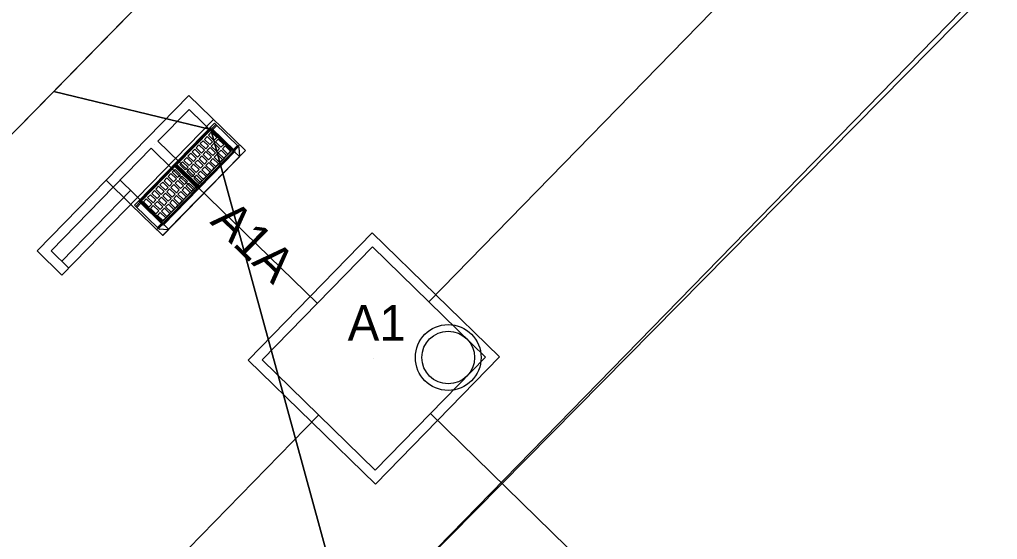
# Model space of a CAD drawing. Extents: x 2251012 to 2259557, y 13786786 to 13792525.
# Drawn here: x 2254977.12 to 2255026.62, y 13790879.97 to 13790906.29 of the extents above; entities that cross this region are included whole.
import ezdxf

# ---------------------------------------------------------------- set-up
doc = ezdxf.new("R2010")
doc.units = 0
for name, color, linetype in [('D_BOXES_1', 7, 'Continuous'), ('D_DRAIN_MISC', 7, 'Continuous'), ('D_DRAIN_NOTES_1', 7, 'Continuous'), ('D_DRN_AREA_A', 7, 'Continuous'), ('D_DRN_AREA_B', 7, 'Continuous'), ('D_DRN_AREA_X', 7, 'Continuous'), ('D_INLET_1', 7, 'Continuous'), ('D_PIPES_1', 7, 'Continuous')]:
    doc.layers.add(name, color=color, linetype=linetype)

msp = doc.modelspace()

# ---------------------------------------------------------------- linework, layer by layer
at = {"layer": 'D_BOXES_1'}
msp.add_line((2254879.145, 13790770.287), (2254992.252, 13790886.265), dxfattribs=at)
msp.add_lwpolyline([(2254997.838, 13790891.992), (2255031.955, 13790926.975), (2255100.904, 13790927.272)], dxfattribs=at)
at = {"layer": 'D_DRAIN_MISC'}
for p, q in [((2254986.768, 13790900.693), (2254986.768, 13790900.693)), ((2254983.948, 13790899.95), (2254983.948, 13790899.95)), ((2254984.843, 13790899.077), (2254984.843, 13790899.077)), ((2254986.096, 13790897.856), (2254986.096, 13790897.856)), ((2254983.277, 13790897.113), (2254983.277, 13790897.113)), ((2254992.181, 13790891.921), (2254992.181, 13790891.921)), ((2254997.838, 13790891.992), (2254997.838, 13790891.992)), ((2254995.045, 13790889.128), (2254995.045, 13790889.128)), ((2254992.252, 13790886.265), (2254992.252, 13790886.265)), ((2254997.909, 13790886.336), (2254997.909, 13790886.336))]:
    msp.add_line(p, q, dxfattribs=at)
at = {"layer": 'D_DRN_AREA_A'}
for p, q in [((2254978.852, 13790902.651), (2254976.227, 13790899.968)), ((2254986.79, 13790900.715), (2254978.852, 13790902.651)), ((2254993.845, 13790875.008), (2254986.79, 13790900.715))]:
    msp.add_line(p, q, dxfattribs=at)
at = {"layer": 'D_DRN_AREA_B'}
for p, q in [((2255005.214, 13790929.644), (2254978.852, 13790902.651)), ((2254978.852, 13790902.651), (2254986.79, 13790900.715)), ((2254986.79, 13790900.715), (2254993.845, 13790875.008))]:
    msp.add_line(p, q, dxfattribs=at)
at = {"layer": 'D_DRN_AREA_X'}
for p, q in [((2255062.918, 13790944.988), (2254993.845, 13790875.008)), ((2255005.214, 13790929.644), (2254978.852, 13790902.651)), ((2254993.845, 13790875.008), (2255037.337, 13790919.603)), ((2254976.227, 13790899.968), (2254982.409, 13790906.286)), ((2254978.852, 13790902.651), (2254976.227, 13790899.968)), ((2254986.79, 13790900.715), (2254978.852, 13790902.651)), ((2254978.852, 13790902.651), (2254986.79, 13790900.715)), ((2254993.845, 13790875.008), (2254986.79, 13790900.715)), ((2254986.79, 13790900.715), (2254993.845, 13790875.008))]:
    msp.add_line(p, q, dxfattribs=at)
at = {"layer": 'D_INLET_1'}
for p, q in [((2254985.685, 13790902.447), (2254978.005, 13790894.572)), ((2254988.549, 13790899.654), (2254985.685, 13790902.447)), ((2254985.694, 13790901.74), (2254984.123, 13790900.129)), ((2254987.842, 13790899.645), (2254985.694, 13790901.74)), ((2254986.938, 13790901.225), (2254979.258, 13790893.35)), ((2254986.986, 13790901.039), (2254983.894, 13790897.869)), ((2254986.808, 13790900.805), (2254985.001, 13790898.953)), ((2254986.813, 13790900.742), (2254985.064, 13790898.949)), ((2254986.81, 13790900.722), (2254985.084, 13790898.952)), ((2254988.025, 13790899.617), (2254986.808, 13790900.805)), ((2254987.943, 13790899.618), (2254986.81, 13790900.722)), ((2254987.962, 13790899.621), (2254986.813, 13790900.742)), ((2254986.842, 13790900.772), (2254987.046, 13790900.981)), ((2254986.893, 13790900.722), (2254987.097, 13790900.931)), ((2254988.216, 13790899.84), (2254986.986, 13790901.039)), ((2254984.123, 13790900.129), (2254986.328, 13790897.979)), ((2254986.406, 13790900.155), (2254986.264, 13790900.009)), ((2254986.406, 13790900.155), (2254986.681, 13790899.887)), ((2254986.614, 13790900.367), (2254986.472, 13790900.222)), ((2254986.472, 13790900.222), (2254986.746, 13790899.954)), ((2254986.614, 13790900.367), (2254986.888, 13790900.1)), ((2254986.821, 13790900.58), (2254986.679, 13790900.435)), ((2254986.679, 13790900.435), (2254986.954, 13790900.167)), ((2254987.096, 13790900.313), (2254986.821, 13790900.58)), ((2254986.954, 13790900.167), (2254987.096, 13790900.313)), ((2254987.031, 13790900.092), (2254987.173, 13790900.238)), ((2254987.449, 13790899.968), (2254987.173, 13790900.238)), ((2254983.774, 13790899.771), (2254978.712, 13790894.581)), ((2254983.774, 13790899.771), (2254985.979, 13790897.621)), ((2254988.248, 13790899.948), (2254984.059, 13790895.652)), ((2254987.842, 13790899.645), (2254984.351, 13790896.066)), ((2254988.546, 13790899.657), (2254984.357, 13790895.362)), ((2254988.549, 13790899.654), (2254984.36, 13790895.359)), ((2254985.991, 13790899.729), (2254985.849, 13790899.583)), ((2254985.991, 13790899.729), (2254986.266, 13790899.461)), ((2254986.199, 13790899.942), (2254986.056, 13790899.796)), ((2254986.056, 13790899.796), (2254986.331, 13790899.528)), ((2254986.199, 13790899.942), (2254986.473, 13790899.674)), ((2254986.264, 13790900.009), (2254986.539, 13790899.741)), ((2254986.331, 13790899.528), (2254986.473, 13790899.674)), ((2254986.539, 13790899.741), (2254986.681, 13790899.887)), ((2254986.615, 13790899.666), (2254986.757, 13790899.812)), ((2254986.615, 13790899.666), (2254986.892, 13790899.397)), ((2254986.746, 13790899.954), (2254986.888, 13790900.1)), ((2254986.757, 13790899.812), (2254987.034, 13790899.542)), ((2254986.823, 13790899.879), (2254986.965, 13790900.025)), ((2254986.823, 13790899.879), (2254987.1, 13790899.609)), ((2254986.965, 13790900.025), (2254987.242, 13790899.755)), ((2254987.031, 13790900.092), (2254987.307, 13790899.822)), ((2254987.1, 13790899.609), (2254987.242, 13790899.755)), ((2254987.176, 13790899.535), (2254987.318, 13790899.68)), ((2254987.307, 13790899.822), (2254987.449, 13790899.968)), ((2254987.318, 13790899.68), (2254987.593, 13790899.413)), ((2254987.384, 13790899.748), (2254987.526, 13790899.893)), ((2254987.384, 13790899.748), (2254987.658, 13790899.48)), ((2254987.801, 13790899.625), (2254987.526, 13790899.893)), ((2254987.94, 13790899.7), (2254988.144, 13790899.91)), ((2254987.991, 13790899.651), (2254988.195, 13790899.86)), ((2254988.27, 13790899.396), (2254988.231, 13790899.809)), ((2254988.26, 13790899.364), (2254984.643, 13790895.655)), ((2254985.576, 13790899.303), (2254985.434, 13790899.157)), ((2254985.434, 13790899.157), (2254985.708, 13790898.89)), ((2254985.576, 13790899.303), (2254985.85, 13790899.035)), ((2254985.783, 13790899.516), (2254985.641, 13790899.37)), ((2254985.641, 13790899.37), (2254985.916, 13790899.103)), ((2254985.783, 13790899.516), (2254986.058, 13790899.248)), ((2254985.849, 13790899.583), (2254986.123, 13790899.315)), ((2254985.916, 13790899.103), (2254986.058, 13790899.248)), ((2254985.993, 13790899.028), (2254986.135, 13790899.173)), ((2254986.123, 13790899.315), (2254986.266, 13790899.461)), ((2254986.135, 13790899.173), (2254986.411, 13790898.904)), ((2254986.2, 13790899.241), (2254986.342, 13790899.386)), ((2254986.2, 13790899.241), (2254986.477, 13790898.971)), ((2254987.962, 13790899.621), (2254986.214, 13790897.828)), ((2254986.216, 13790897.848), (2254987.943, 13790899.618)), ((2254988.025, 13790899.617), (2254986.219, 13790897.765)), ((2254986.342, 13790899.386), (2254986.619, 13790899.116)), ((2254987.93, 13790899.564), (2254986.357, 13790897.951)), ((2254986.408, 13790899.454), (2254986.55, 13790899.599)), ((2254986.408, 13790899.454), (2254986.684, 13790899.184)), ((2254986.55, 13790899.599), (2254986.827, 13790899.329)), ((2254986.684, 13790899.184), (2254986.827, 13790899.329)), ((2254986.761, 13790899.109), (2254986.903, 13790899.255)), ((2254986.892, 13790899.397), (2254987.034, 13790899.542)), ((2254986.903, 13790899.255), (2254987.178, 13790898.987)), ((2254986.969, 13790899.322), (2254987.111, 13790899.467)), ((2254986.969, 13790899.322), (2254987.243, 13790899.054)), ((2254987.111, 13790899.467), (2254987.385, 13790899.2)), ((2254987.176, 13790899.535), (2254987.451, 13790899.267)), ((2254987.243, 13790899.054), (2254987.385, 13790899.2)), ((2254987.451, 13790899.267), (2254987.593, 13790899.413)), ((2254987.658, 13790899.48), (2254987.801, 13790899.625)), ((2254987.996, 13790899.588), (2254988.243, 13790899.347)), ((2254983.166, 13790897.07), (2254984.972, 13790898.923)), ((2254983.229, 13790897.067), (2254984.977, 13790898.86)), ((2254983.248, 13790897.07), (2254984.975, 13790898.84)), ((2254984.844, 13790898.553), (2254984.986, 13790898.698)), ((2254986.19, 13790897.735), (2254984.972, 13790898.923)), ((2254986.107, 13790897.736), (2254984.975, 13790898.84)), ((2254986.127, 13790897.739), (2254984.977, 13790898.86)), ((2254985.26, 13790898.43), (2254984.986, 13790898.698)), ((2254986.219, 13790897.765), (2254985.001, 13790898.953)), ((2254986.214, 13790897.828), (2254985.064, 13790898.949)), ((2254986.216, 13790897.848), (2254985.084, 13790898.952)), ((2254985.368, 13790899.09), (2254985.226, 13790898.945)), ((2254985.501, 13790898.677), (2254985.226, 13790898.945)), ((2254985.368, 13790899.09), (2254985.643, 13790898.822)), ((2254985.501, 13790898.677), (2254985.643, 13790898.822)), ((2254985.577, 13790898.602), (2254985.719, 13790898.748)), ((2254985.708, 13790898.89), (2254985.85, 13790899.035)), ((2254985.719, 13790898.748), (2254985.996, 13790898.478)), ((2254985.785, 13790898.815), (2254985.927, 13790898.961)), ((2254985.785, 13790898.815), (2254986.062, 13790898.545)), ((2254985.927, 13790898.961), (2254986.204, 13790898.691)), ((2254985.993, 13790899.028), (2254986.269, 13790898.758)), ((2254986.062, 13790898.545), (2254986.204, 13790898.691)), ((2254986.269, 13790898.758), (2254986.411, 13790898.904)), ((2254986.346, 13790898.683), (2254986.488, 13790898.829)), ((2254986.346, 13790898.683), (2254986.62, 13790898.415)), ((2254986.477, 13790898.971), (2254986.619, 13790899.116)), ((2254986.488, 13790898.829), (2254986.763, 13790898.561)), ((2254986.553, 13790898.896), (2254986.696, 13790899.042)), ((2254986.553, 13790898.896), (2254986.828, 13790898.628)), ((2254986.696, 13790899.042), (2254986.97, 13790898.774)), ((2254986.761, 13790899.109), (2254987.036, 13790898.841)), ((2254986.828, 13790898.628), (2254986.97, 13790898.774)), ((2254987.036, 13790898.841), (2254987.178, 13790898.987)), ((2254982.749, 13790896.93), (2254981.496, 13790898.152)), ((2254984.351, 13790896.066), (2254982.203, 13790898.16)), ((2254984.428, 13790898.127), (2254984.571, 13790898.272)), ((2254984.571, 13790898.272), (2254984.845, 13790898.005)), ((2254984.636, 13790898.34), (2254984.778, 13790898.485)), ((2254984.636, 13790898.34), (2254984.911, 13790898.072)), ((2254984.778, 13790898.485), (2254985.053, 13790898.217)), ((2254984.844, 13790898.553), (2254985.118, 13790898.285)), ((2254985.053, 13790898.217), (2254984.911, 13790898.072)), ((2254985.26, 13790898.43), (2254985.118, 13790898.285)), ((2254985.337, 13790898.356), (2254985.195, 13790898.21)), ((2254985.195, 13790898.21), (2254985.472, 13790897.94)), ((2254985.614, 13790898.086), (2254985.337, 13790898.356)), ((2254985.854, 13790898.332), (2254985.577, 13790898.602)), ((2254985.854, 13790898.332), (2254985.996, 13790898.478)), ((2254985.931, 13790898.257), (2254986.073, 13790898.403)), ((2254986.205, 13790897.99), (2254985.931, 13790898.257)), ((2254986.073, 13790898.403), (2254986.347, 13790898.135)), ((2254986.138, 13790898.47), (2254986.28, 13790898.616)), ((2254986.138, 13790898.47), (2254986.413, 13790898.203)), ((2254986.28, 13790898.616), (2254986.555, 13790898.348)), ((2254986.413, 13790898.203), (2254986.555, 13790898.348)), ((2254986.62, 13790898.415), (2254986.763, 13790898.561)), ((2254983.894, 13790897.869), (2254982.936, 13790896.886)), ((2254984.013, 13790897.701), (2254984.155, 13790897.847)), ((2254984.013, 13790897.701), (2254984.288, 13790897.433)), ((2254984.155, 13790897.847), (2254984.43, 13790897.579)), ((2254984.221, 13790897.914), (2254984.363, 13790898.06)), ((2254984.221, 13790897.914), (2254984.495, 13790897.646)), ((2254984.363, 13790898.06), (2254984.638, 13790897.792)), ((2254984.378, 13790895.946), (2254986.127, 13790897.739)), ((2254986.107, 13790897.736), (2254984.381, 13790895.965)), ((2254984.383, 13790895.883), (2254986.19, 13790897.735)), ((2254984.428, 13790898.127), (2254984.703, 13790897.859)), ((2254984.638, 13790897.792), (2254984.495, 13790897.646)), ((2254984.714, 13790897.717), (2254984.572, 13790897.571)), ((2254984.845, 13790898.005), (2254984.703, 13790897.859)), ((2254984.714, 13790897.717), (2254984.991, 13790897.447)), ((2254984.922, 13790897.93), (2254984.78, 13790897.784)), ((2254984.78, 13790897.784), (2254985.056, 13790897.514)), ((2254984.922, 13790897.93), (2254985.198, 13790897.66)), ((2254985.129, 13790898.143), (2254984.987, 13790897.997)), ((2254984.987, 13790897.997), (2254985.264, 13790897.727)), ((2254985.198, 13790897.66), (2254985.056, 13790897.514)), ((2254985.129, 13790898.143), (2254985.406, 13790897.873)), ((2254985.406, 13790897.873), (2254985.264, 13790897.727)), ((2254985.483, 13790897.798), (2254985.341, 13790897.652)), ((2254985.341, 13790897.652), (2254985.615, 13790897.385)), ((2254985.614, 13790898.086), (2254985.472, 13790897.94)), ((2254985.483, 13790897.798), (2254985.757, 13790897.53)), ((2254985.69, 13790898.011), (2254985.548, 13790897.865)), ((2254985.548, 13790897.865), (2254985.823, 13790897.598)), ((2254985.965, 13790897.743), (2254985.69, 13790898.011)), ((2254985.965, 13790897.743), (2254985.823, 13790897.598)), ((2254986.205, 13790897.99), (2254986.347, 13790898.135)), ((2254982.74, 13790897.637), (2254979.249, 13790894.057)), ((2254983.39, 13790897.062), (2254983.533, 13790897.208)), ((2254983.533, 13790897.208), (2254983.807, 13790896.94)), ((2254983.598, 13790897.275), (2254983.74, 13790897.421)), ((2254983.598, 13790897.275), (2254983.873, 13790897.007)), ((2254983.74, 13790897.421), (2254984.015, 13790897.153)), ((2254983.806, 13790897.488), (2254983.948, 13790897.634)), ((2254983.806, 13790897.488), (2254984.08, 13790897.22)), ((2254983.948, 13790897.634), (2254984.222, 13790897.366)), ((2254984.222, 13790897.366), (2254984.08, 13790897.22)), ((2254984.299, 13790897.291), (2254984.157, 13790897.146)), ((2254984.43, 13790897.579), (2254984.288, 13790897.433)), ((2254984.299, 13790897.291), (2254984.576, 13790897.021)), ((2254984.507, 13790897.504), (2254984.365, 13790897.358)), ((2254984.365, 13790897.358), (2254984.641, 13790897.089)), ((2254986.007, 13790897.593), (2254984.434, 13790895.979)), ((2254984.507, 13790897.504), (2254984.783, 13790897.234)), ((2254984.572, 13790897.571), (2254984.849, 13790897.301)), ((2254984.783, 13790897.234), (2254984.641, 13790897.089)), ((2254984.86, 13790897.16), (2254984.718, 13790897.014)), ((2254984.991, 13790897.447), (2254984.849, 13790897.301)), ((2254984.86, 13790897.16), (2254985.135, 13790896.892)), ((2254985.068, 13790897.372), (2254984.925, 13790897.227)), ((2254984.925, 13790897.227), (2254985.2, 13790896.959)), ((2254985.068, 13790897.372), (2254985.342, 13790897.105)), ((2254985.275, 13790897.585), (2254985.133, 13790897.44)), ((2254985.133, 13790897.44), (2254985.408, 13790897.172)), ((2254985.275, 13790897.585), (2254985.55, 13790897.317)), ((2254985.55, 13790897.317), (2254985.408, 13790897.172)), ((2254985.757, 13790897.53), (2254985.615, 13790897.385)), ((2254984.36, 13790895.359), (2254982.749, 13790896.93)), ((2254984.166, 13790895.687), (2254982.936, 13790896.886)), ((2254983.2, 13790897.037), (2254982.996, 13790896.828)), ((2254983.251, 13790896.987), (2254983.047, 13790896.778)), ((2254984.383, 13790895.883), (2254983.166, 13790897.07)), ((2254984.378, 13790895.946), (2254983.229, 13790897.067)), ((2254984.381, 13790895.965), (2254983.248, 13790897.07)), ((2254983.665, 13790896.795), (2254983.39, 13790897.062)), ((2254983.807, 13790896.94), (2254983.665, 13790896.795)), ((2254983.884, 13790896.866), (2254983.742, 13790896.72)), ((2254984.018, 13790896.45), (2254983.742, 13790896.72)), ((2254984.015, 13790897.153), (2254983.873, 13790897.007)), ((2254983.884, 13790896.866), (2254984.16, 13790896.596)), ((2254984.091, 13790897.078), (2254983.949, 13790896.933)), ((2254983.949, 13790896.933), (2254984.226, 13790896.663)), ((2254984.091, 13790897.078), (2254984.368, 13790896.809)), ((2254984.157, 13790897.146), (2254984.434, 13790896.876)), ((2254984.368, 13790896.809), (2254984.226, 13790896.663)), ((2254984.445, 13790896.734), (2254984.303, 13790896.588)), ((2254984.576, 13790897.021), (2254984.434, 13790896.876)), ((2254984.445, 13790896.734), (2254984.719, 13790896.466)), ((2254984.652, 13790896.947), (2254984.51, 13790896.801)), ((2254984.51, 13790896.801), (2254984.785, 13790896.533)), ((2254984.652, 13790896.947), (2254984.927, 13790896.679)), ((2254984.718, 13790897.014), (2254984.992, 13790896.746)), ((2254984.927, 13790896.679), (2254984.785, 13790896.533)), ((2254985.135, 13790896.892), (2254984.992, 13790896.746)), ((2254985.342, 13790897.105), (2254985.2, 13790896.959)), ((2254984.16, 13790896.596), (2254984.018, 13790896.45)), ((2254984.237, 13790896.521), (2254984.095, 13790896.375)), ((2254984.37, 13790896.107), (2254984.095, 13790896.375)), ((2254984.237, 13790896.521), (2254984.512, 13790896.253)), ((2254984.303, 13790896.588), (2254984.577, 13790896.32)), ((2254984.512, 13790896.253), (2254984.37, 13790896.107)), ((2254984.719, 13790896.466), (2254984.577, 13790896.32)), ((2254984.298, 13790895.966), (2254984.094, 13790895.757)), ((2254984.349, 13790895.916), (2254984.145, 13790895.707)), ((2254984.611, 13790895.643), (2254984.197, 13790895.672)), ((2254984.412, 13790895.913), (2254984.659, 13790895.672)), ((2254988.682, 13790889.049), (2254994.965, 13790895.492)), ((2254994.965, 13790895.492), (2255001.408, 13790889.208)), ((2254989.389, 13790889.057), (2254994.974, 13790894.785)), ((2254994.974, 13790894.785), (2255000.701, 13790889.199)), ((2254978.005, 13790894.572), (2254979.258, 13790893.35)), ((2254978.712, 13790894.581), (2254979.607, 13790893.708)), ((2254995.125, 13790882.765), (2254988.682, 13790889.049)), ((2254995.116, 13790883.472), (2254989.389, 13790889.057)), ((2255000.701, 13790889.199), (2254995.116, 13790883.472)), ((2255001.408, 13790889.208), (2254995.125, 13790882.765))]:
    msp.add_line(p, q, dxfattribs=at)
for radius in [1.666, 1.333]:
    msp.add_circle((2254998.816, 13790889.176), radius, dxfattribs=at)
for centre, start_param, end_param in [((2254988.186, 13790899.81), 0.80294, 1.570796), ((2254988.226, 13790899.397), 0, 0.80294), ((2254984.195, 13790895.717), 4.712389, 5.480245), ((2254984.608, 13790895.688), 5.480245, 6.283185)]:
    msp.add_ellipse(centre, major_axis=(0.0341, -0.0332), ratio=0.877193, start_param=start_param, end_param=end_param, dxfattribs=at)
at = {"layer": 'D_PIPES_1'}
for p, q in [((2254986.096, 13790897.856), (2254992.181, 13790891.921)), ((2255016.88, 13790867.833), (2254997.909, 13790886.336))]:
    msp.add_line(p, q, dxfattribs=at)

# ---------------------------------------------------------------- texts
at = {"layer": 'D_DRAIN_NOTES_1'}
msp.add_text('A1A', height=1.8, rotation=315.7179, dxfattribs=at).set_placement((2254986.705, 13790896.005))
msp.add_text('A1', height=1.8, dxfattribs=at).set_placement((2254993.723, 13790890.028))

doc.saveas('drawing.dxf')
